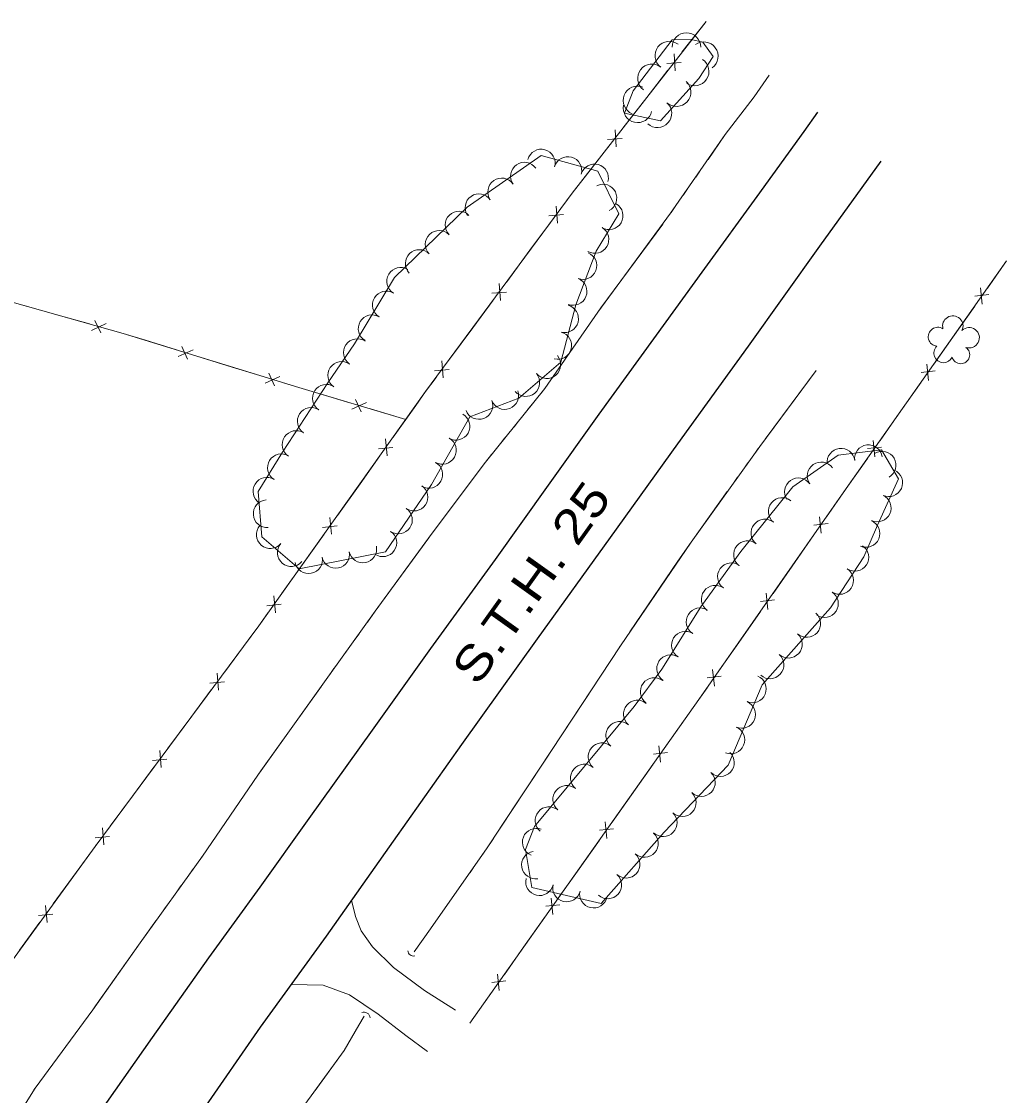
# Model space of a CAD drawing. Extents: x 296677 to 299172, y 46050 to 48373.
# Drawn here: x 298156.8 to 298443.9, y 47221.8 to 47534.8 of the extents above; entities that cross this region are included whole.
import ezdxf

# ---------------------------------------------------------------- set-up
doc = ezdxf.new("R2010")
doc.units = 0
doc.header["$LTSCALE"] = 2.4
doc.linetypes.add('LONG_DASHED', pattern=[7.5, 6, -1.5])
for name, color, linetype, lineweight in [('11', 7, 'Continuous', 25), ('15', 7, 'Continuous', 13), ('17', 7, 'LONG_DASHED', 13), ('18', 7, 'Continuous', 13), ('19', 7, 'Continuous', 13)]:
    doc.layers.add(name, color=color, linetype=linetype, lineweight=lineweight)

msp = doc.modelspace()

# ---------------------------------------------------------------- linework, layer by layer
at = {"layer": '11'}
for points in [[(298144.819, 47166.218), (298158.695, 47187.074), (298169.307, 47202.119), (298181.702, 47219.814), (298194.94, 47238.763), (298211.359, 47261.966), (298226.359, 47282.562), (298240.69, 47302.559), (298259.095, 47328.281), (298276.105, 47352.106), (298294.952, 47377.993), (298310.4, 47399.704), (298325.208, 47420.351), (298341.132, 47442.362), (298355.987, 47462.841), (298371.207, 47483.789), (298384.92, 47502.725), (298388.911, 47508.371)], [(298019.649, 46909.369), (298032.706, 46934.301), (298046.486, 46959.382), (298060.266, 46984.166), (298075.743, 47010.457), (298090.987, 47036.558), (298105.83, 47061.356), (298119.928, 47084.202), (298135.395, 47108.043), (298152.172, 47133.361), (298169.529, 47159.369), (298189.917, 47189.118), (298209.655, 47217.416), (298226.429, 47241.723), (298245.674, 47268.289), (298265.185, 47295.988), (298285.166, 47324.097), (298307.161, 47354.894), (298328.486, 47384.422), (298348.071, 47411.701), (298368.67, 47440.188), (298389.533, 47469.344), (298407.334, 47494.128)]]:
    msp.add_lwpolyline(points, dxfattribs=at)
at = {"layer": '15'}
for p, q in [((298349.315, 47525.805), (298356.323, 47534.793)), ((298347.34, 47520.423), (298347.069, 47525.379)), ((298344.873, 47522.563), (298349.122, 47522.82)), ((298339.077, 47512.673), (298345.241, 47520.579)), ((298332.07, 47503.685), (298339.077, 47512.673)), ((298330.094, 47498.304), (298329.823, 47503.26)), ((298327.628, 47500.444), (298331.876, 47500.701)), ((298321.832, 47490.554), (298327.995, 47498.459)), ((298313.073, 47476.071), (298312.674, 47481.018)), ((298310.552, 47478.146), (298314.792, 47478.513)), ((298305.015, 47468.108), (298310.971, 47476.171)), ((298298.243, 47458.941), (298305.015, 47468.108)), ((298443.923, 47465.07), (298438.334, 47457.126)), ((298293.887, 47455.585), (298298.127, 47455.952)), ((298296.408, 47453.51), (298296.009, 47458.457)), ((298436.295, 47457.177), (298436.793, 47452.393)), ((298288.35, 47445.548), (298294.306, 47453.611)), ((298438.784, 47455.223), (298434.685, 47454.772)), ((298157.149, 47452.124), (298167.494, 47449.212)), ((298167.494, 47449.212), (298176.593, 47446.651)), ((298434.639, 47451.875), (298428.284, 47442.843)), ((298177.206, 47444.764), (298181.436, 47446.768)), ((298178.195, 47447.68), (298179.934, 47444.063)), ((298281.579, 47436.38), (298288.35, 47445.548)), ((298192.907, 47441.887), (298201.94, 47439.103)), ((298203.566, 47440.092), (298205.216, 47436.433)), ((298428.284, 47442.843), (298422.695, 47434.899)), ((298202.506, 47437.201), (298206.784, 47439.1)), ((298207.912, 47437.263), (298218.183, 47434.097)), ((298218.183, 47434.097), (298227.216, 47431.313)), ((298279.744, 47430.949), (298279.344, 47435.897)), ((298420.657, 47434.95), (298421.154, 47430.166)), ((298227.782, 47429.411), (298232.06, 47431.311)), ((298228.842, 47432.302), (298230.492, 47428.644)), ((298277.222, 47433.025), (298281.463, 47433.392)), ((298423.145, 47432.996), (298419.046, 47432.546)), ((298419, 47429.648), (298412.646, 47420.616)), ((298243.477, 47426.368), (298252.538, 47423.678)), ((298254.154, 47424.684), (298255.842, 47421.043)), ((298253.124, 47421.782), (298257.382, 47423.726)), ((298258.529, 47421.9), (298268.832, 47418.842)), ((298265.137, 47413.658), (298271.753, 47422.939)), ((298412.646, 47420.616), (298407.056, 47412.673)), ((298263.395, 47408.196), (298262.911, 47413.136)), ((298405.018, 47412.723), (298405.515, 47407.94)), ((298260.839, 47410.228), (298265.072, 47410.668)), ((298407.506, 47410.769), (298403.407, 47410.319)), ((298255.473, 47400.099), (298261.291, 47408.262)), ((298248.857, 47390.818), (298255.473, 47400.099)), ((298397.008, 47398.389), (298391.442, 47390.428)), ((298247.115, 47385.357), (298246.631, 47390.297)), ((298389.404, 47390.473), (298389.915, 47385.691)), ((298244.559, 47387.389), (298248.792, 47387.828)), ((298391.898, 47388.527), (298387.8, 47388.064)), ((298239.193, 47377.259), (298245.011, 47385.422)), ((298387.763, 47385.166), (298381.435, 47376.115)), ((298232.577, 47367.978), (298239.193, 47377.259)), ((298381.435, 47376.115), (298375.87, 47368.155)), ((298373.831, 47368.2), (298374.343, 47363.418)), ((298228.278, 47364.549), (298232.512, 47364.988)), ((298230.834, 47362.517), (298230.351, 47367.457)), ((298376.326, 47366.253), (298372.228, 47365.79)), ((298372.191, 47362.893), (298365.863, 47353.842)), ((298216.04, 47345.326), (298222.831, 47354.479)), ((298365.863, 47353.842), (298360.298, 47345.882)), ((298358.259, 47345.926), (298358.771, 47341.144)), ((298214.193, 47339.899), (298213.804, 47344.847)), ((298360.753, 47343.98), (298356.655, 47343.517)), ((298206.118, 47331.954), (298212.091, 47340.004)), ((298211.676, 47341.979), (298215.917, 47342.338)), ((298199.327, 47322.801), (298206.118, 47331.954)), ((298350.258, 47331.592), (298344.646, 47323.664)), ((298197.48, 47317.374), (298197.091, 47322.322)), ((298345.091, 47321.759), (298340.99, 47321.32)), ((298342.608, 47323.72), (298343.092, 47318.935)), ((298194.963, 47319.455), (298199.204, 47319.813)), ((298340.937, 47318.423), (298334.556, 47309.409)), ((298189.405, 47309.429), (298195.378, 47317.479)), ((298182.614, 47300.276), (298189.405, 47309.429)), ((298334.556, 47309.409), (298328.944, 47301.481)), ((298180.767, 47294.849), (298180.378, 47299.798)), ((298329.389, 47299.577), (298325.289, 47299.138)), ((298326.906, 47301.538), (298327.39, 47296.753)), ((298178.25, 47296.93), (298182.491, 47297.288)), ((298325.235, 47296.241), (298318.854, 47287.227)), ((298166.037, 47277.651), (298172.754, 47286.859)), ((298318.854, 47287.227), (298313.243, 47279.299)), ((298164.235, 47272.209), (298163.806, 47277.154)), ((298313.687, 47277.395), (298309.587, 47276.956)), ((298311.204, 47279.355), (298311.688, 47274.57)), ((298161.702, 47274.269), (298165.94, 47274.662)), ((298309.533, 47274.058), (298303.153, 47265.044)), ((298156.226, 47264.198), (298162.133, 47272.297)), ((298303.153, 47265.044), (298297.541, 47257.117)), ((298297.986, 47255.212), (298293.885, 47254.773)), ((298295.503, 47257.173), (298295.987, 47252.388)), ((298293.831, 47251.876), (298287.451, 47242.862))]:
    msp.add_line(p, q, dxfattribs=at)
for points in [[(297934.044, 46907.735), (297975.364, 46985.334), (298019.861, 47066.957), (298074.609, 47150.346), (298125.783, 47222.46), (298178.264, 47294.414), (298225.978, 47358.72), (298274.598, 47426.93), (298317.324, 47484.772), (298356.323, 47534.793)], [(298042.529, 47491.507), (298087.491, 47471.635), (298107.15, 47466.195), (298186.423, 47443.885), (298237.649, 47428.098), (298268.832, 47418.842)], [(298314.908, 47481.501), (298317.324, 47484.772), (298321.832, 47490.554)], [(298443.923, 47465.07), (298397.2, 47398.664), (298354.246, 47337.226), (298287.451, 47242.862)], [(298182.608, 47444.959), (298186.423, 47443.885), (298192.907, 47441.887)], [(298271.753, 47422.939), (298274.598, 47426.93), (298277.642, 47431.05)], [(298233.187, 47429.473), (298237.649, 47428.098), (298243.477, 47426.368)], [(298403.362, 47407.421), (298397.2, 47398.664), (298397.008, 47398.389)], [(298222.831, 47354.479), (298225.978, 47358.72), (298228.731, 47362.582)], [(298356.619, 47340.619), (298354.246, 47337.226), (298350.258, 47331.592)], [(298172.754, 47286.859), (298178.264, 47294.414), (298178.665, 47294.955)]]:
    msp.add_lwpolyline(points, dxfattribs=at)
for centre, radius, start, end in [((298270.984, 47264.039), 1.572, 180.22374, 286.46331), ((298256.634, 47244.296), 1.819, 5.64214, 111.88171)]:
    msp.add_arc(centre, radius, start, end, dxfattribs=at)
at = {"layer": '17'}
for points in [[(298283.319, 47246.66), (298274.283, 47252.382), (298265.205, 47259.152), (298259.09, 47265.157), (298255.821, 47269.848), (298254.131, 47273.971), (298253.027, 47278.728)], [(298235.42, 47254.134), (298244.685, 47253.981), (298252.402, 47251.192), (298260.795, 47245.485), (298268.79, 47239.359), (298275.107, 47234.605)]]:
    msp.add_lwpolyline(points, dxfattribs=at)
at = {"layer": '18'}
for points in [[(298346.425, 47529.485), (298335.078, 47514.566), (298332.53, 47508.085), (298343.077, 47505.811), (298354.279, 47518.184), (298358.455, 47524.555), (298355.404, 47528.747), (298351.967, 47529.499)], [(298232.859, 47409.299), (298225.764, 47397.796), (298226.806, 47384.622), (298237.752, 47375.251), (298262.88, 47380.238), (298276.283, 47399.897), (298287.443, 47419.61), (298301.761, 47425.066), (298314.031, 47435.526), (298318.335, 47452.24), (298324.353, 47467.824), (298330.887, 47478.756), (298324.777, 47491.144), (298308.319, 47495.727), (298286.724, 47480.724), (298265.481, 47460.176), (298253.906, 47440.873), (298246.078, 47429.524)], [(298306.352, 47300.17), (298303.713, 47293.475), (298305.546, 47282.478), (298325.747, 47277.826), (298344.148, 47298.588), (298362.769, 47318.135), (298372.656, 47341.527), (298392.568, 47363.94), (298402.348, 47378.82), (298406.272, 47388.011), (298412.428, 47401.483), (298407.47, 47409.997), (298394.823, 47408.393), (298381.673, 47399.225), (298366.446, 47380.37), (298354.834, 47364.244), (298343.448, 47346.079), (298335.358, 47335.144)]]:
    msp.add_lwpolyline(points, close=True, dxfattribs=at)
for centre, radius, start, end in [((298350.599, 47527.313), 4.17, 0.1524, 180.13708), ((298345.638, 47524.845), 4.17, 52.75199, 232.73667), ((298355.668, 47524.675), 4.17, 306.05535, 126.04003), ((298340.59, 47518.207), 4.17, 52.75199, 232.73667), ((298353.011, 47520.23), 4.17, 236.76402, 56.7487), ((298336.339, 47511.809), 4.17, 68.54543, 248.53011), ((298347.746, 47514.22), 4.17, 227.85128, 47.83596), ((298336.391, 47509.485), 4.17, 167.84058, 347.82526), ((298342.149, 47508.038), 4.17, 227.85128, 47.83596), ((298308.307, 47493.54), 4.031, 344.44693, 164.43161), ((298303.375, 47489.723), 4.031, 34.79708, 214.78176), ((298316.072, 47491.378), 4.031, 344.44693, 164.43161), ((298323.838, 47489.216), 4.031, 344.44693, 164.43161), ((298296.755, 47485.124), 4.031, 34.79708, 214.78176), ((298326.279, 47483.329), 4.031, 296.26106, 116.24574), ((298290.135, 47480.525), 4.031, 34.79708, 214.78176), ((298328.091, 47478.189), 4.031, 239.14112, 59.1258), ((298284.329, 47475.472), 4.031, 44.0549, 224.03958), ((298323.955, 47471.27), 4.031, 239.14112, 59.1258), ((298278.535, 47469.868), 4.031, 44.0549, 224.03958), ((298272.741, 47464.263), 4.031, 44.0549, 224.03958), ((298320.473, 47463.634), 4.031, 248.89283, 68.87751), ((298267.29, 47459.09), 4.031, 59.05875, 239.04343), ((298317.569, 47456.114), 4.031, 248.89283, 68.87751), ((298263.145, 47452.177), 4.031, 59.05875, 239.04343), ((298258.999, 47445.264), 4.031, 59.05875, 239.04343), ((298315.114, 47448.193), 4.031, 255.56723, 75.55191), ((298428.267, 47446.035), 2.974, 334.0166, 195.25048), ((298313.104, 47440.386), 4.031, 255.56723, 75.55191), ((298423.885, 47442.924), 2.777, 56.98749, 264.76048), ((298433.034, 47442.636), 2.975, 251.66742, 134.64069), ((298254.691, 47438.296), 4.031, 55.4116, 235.39628), ((298425.553, 47438.145), 2.783, 133.66451, 334.67555), ((298430.574, 47437.691), 2.611, 196.37265, 54.30526), ((298309.934, 47434.806), 4.031, 220.45478, 40.43946), ((298250.114, 47431.66), 4.031, 55.4116, 235.39628), ((298303.8, 47429.576), 4.031, 220.45478, 40.43946), ((298245.65, 47425.013), 4.031, 56.83915, 236.82383), ((298290.129, 47422.891), 4.031, 200.86744, 20.85212), ((298297.661, 47425.761), 4.031, 200.86744, 20.85212), ((298241.24, 47418.265), 4.031, 56.83915, 236.82383), ((298283.448, 47416.836), 4.031, 240.49242, 60.4771), ((298236.83, 47411.518), 4.031, 56.83915, 236.82383), ((298279.477, 47409.821), 4.031, 240.49242, 60.4771), ((298232.539, 47404.761), 4.031, 58.34156, 238.32624), ((298395.668, 47406.372), 4.035, 7.23581, 187.22049), ((298403.673, 47407.387), 4.035, 7.23581, 187.22049), ((298407.645, 47405.501), 4.035, 300.2214, 120.20608), ((298275.506, 47402.806), 4.031, 240.49242, 60.4771), ((298389.891, 47402.38), 4.035, 34.89134, 214.87602), ((298409.597, 47400.369), 4.035, 245.44974, 65.43442), ((298228.307, 47397.9), 4.031, 58.34156, 238.32624), ((298271.209, 47396.201), 4.031, 235.7225, 55.70718), ((298383.272, 47397.766), 4.035, 34.89134, 214.87602), ((298378.547, 47391.992), 4.035, 51.08387, 231.06854), ((298406.244, 47393.031), 4.035, 245.44974, 65.43442), ((298228.39, 47391.346), 4.031, 94.53007, 274.51474), ((298266.669, 47389.54), 4.031, 235.7225, 55.70718), ((298373.477, 47385.715), 4.035, 51.08387, 231.06854), ((298229.305, 47385.26), 4.031, 139.44044, 319.42512), ((298402.95, 47385.608), 4.035, 246.88812, 66.87279), ((298262.128, 47382.88), 4.031, 235.7225, 55.70718), ((298368.408, 47379.438), 4.035, 51.08387, 231.06854), ((298235.428, 47380.018), 4.031, 139.44044, 319.42512), ((298256.289, 47381.081), 4.031, 191.23294, 11.21762), ((298399.71, 47378.651), 4.035, 236.69242, 56.6771), ((298240.475, 47377.942), 4.031, 191.23294, 11.21762), ((298248.382, 47379.512), 4.031, 191.23294, 11.21762), ((298363.741, 47373), 4.035, 54.25078, 234.23546), ((298395.278, 47371.909), 4.035, 236.69242, 56.6771), ((298359.026, 47366.452), 4.035, 54.25078, 234.23546), ((298390.847, 47365.166), 4.035, 236.69242, 56.6771), ((298354.591, 47359.88), 4.035, 57.92777, 237.91245), ((298385.683, 47359.37), 4.035, 228.38936, 48.37404), ((298350.306, 47353.044), 4.035, 57.92777, 237.91245), ((298380.324, 47353.338), 4.035, 228.38936, 48.37404), ((298346.021, 47346.207), 4.035, 57.92777, 237.91245), ((298374.965, 47347.306), 4.035, 228.38936, 48.37404), ((298341.224, 47339.522), 4.035, 53.51265, 233.49733), ((298369.849, 47340.309), 4.035, 247.09554, 67.08022), ((298336.307, 47332.98), 4.035, 50.33674, 230.32142), ((298366.707, 47332.877), 4.035, 247.09554, 67.08022), ((298331.156, 47326.769), 4.035, 50.33674, 230.32142), ((298363.566, 47325.445), 4.035, 247.09554, 67.08022), ((298326.005, 47320.559), 4.035, 50.33674, 230.32142), ((298360.533, 47318.85), 4.035, 226.39745, 46.38213), ((298320.854, 47314.348), 4.035, 50.33674, 230.32142), ((298354.968, 47313.008), 4.035, 226.39745, 46.38213), ((298315.703, 47308.137), 4.035, 50.33674, 230.32142), ((298349.403, 47307.165), 4.035, 226.39745, 46.38213), ((298310.553, 47301.927), 4.035, 50.33674, 230.32142), ((298343.837, 47301.323), 4.035, 226.39745, 46.38213), ((298306.837, 47295.642), 4.035, 68.49456, 248.47923), ((298338.387, 47295.272), 4.035, 228.45765, 48.44232), ((298306.603, 47288.982), 4.035, 99.47083, 279.45551), ((298333.036, 47289.234), 4.035, 228.45765, 48.44232), ((298307.8, 47284.126), 4.035, 167.03936, 347.02403), ((298327.684, 47283.195), 4.035, 228.45765, 48.44232), ((298315.663, 47282.315), 4.035, 167.03936, 347.02403), ((298323.526, 47280.505), 4.035, 167.03936, 347.02403)]:
    msp.add_arc(centre, radius, start, end, dxfattribs=at)
at = {"layer": '19'}
for p, q in [((298353.336, 47489.46), (298354.53, 47491.179)), ((298349.755, 47484.301), (298350.949, 47486.02)), ((298346.174, 47479.142), (298347.368, 47480.861)), ((298325.664, 47451.349), (298343.694, 47475.769)), ((298373.592, 47413.112), (298388.409, 47433.121)), ((298304.295, 47421.612), (298305.609, 47423.242)), ((298300.355, 47416.721), (298301.668, 47418.351)), ((298296.415, 47411.831), (298297.728, 47413.461)), ((298370.554, 47408.953), (298371.557, 47410.347)), ((298367.546, 47404.77), (298368.549, 47406.165)), ((298364.539, 47400.588), (298365.541, 47401.982)), ((298334.141, 47356.895), (298348.143, 47377.484)), ((298253.979, 47354.7), (298255.202, 47356.398)), ((298250.309, 47349.605), (298251.533, 47351.303)), ((298328.413, 47348.332), (298329.358, 47349.766)), ((298246.64, 47344.51), (298247.863, 47346.208)), ((298325.578, 47344.03), (298326.523, 47345.464)), ((298226.576, 47316.397), (298244.207, 47341.102)), ((298296.258, 47299.601), (298309.985, 47320.374)), ((298293.418, 47295.304), (298294.365, 47296.736)), ((298290.493, 47291.064), (298291.48, 47292.469)), ((298205.719, 47286.286), (298206.94, 47287.986)), ((298287.531, 47286.848), (298288.519, 47288.253)), ((298202.055, 47281.185), (298203.276, 47282.886)), ((298198.392, 47276.084), (298199.613, 47277.785))]:
    msp.add_line(p, q, dxfattribs=at)
for points in [[(298147.625, 47203.168), (298160.73, 47224.002), (298177.602, 47246.84), (298191.385, 47266.329), (298209.526, 47291.587), (298225.683, 47315.146), (298246.578, 47344.424), (298259.93, 47362.962), (298276.211, 47385.269), (298291.999, 47406.35), (298309.331, 47427.862), (298324.753, 47450.116), (298346.019, 47478.918), (298361.946, 47501.864), (298370.33, 47512.82), (298374.73, 47519.182)], [(298356.917, 47494.618), (298361.946, 47501.864), (298370.33, 47512.82), (298374.73, 47519.182)], [(298308.236, 47426.502), (298309.331, 47427.862), (298324.753, 47450.116), (298325.664, 47451.349)], [(298271.269, 47263.68), (298276.007, 47270.442), (298292.575, 47294.028), (298311.323, 47322.399), (298331.403, 47352.869), (298351.962, 47383.101), (298371.982, 47410.938), (298388.409, 47433.121)], [(298275.524, 47384.327), (298276.211, 47385.269), (298291.999, 47406.35), (298293.788, 47408.57)], [(298348.143, 47377.484), (298351.962, 47383.101), (298362.534, 47397.8)], [(298257.649, 47359.795), (298259.93, 47362.962), (298275.524, 47384.327)], [(298331.248, 47352.633), (298331.403, 47352.869), (298332.21, 47354.055)], [(298309.985, 47320.374), (298311.323, 47322.399), (298323.688, 47341.163)], [(298209.382, 47291.387), (298209.526, 47291.587), (298225.683, 47315.146), (298226.576, 47316.397)], [(298271.269, 47263.68), (298276.007, 47270.442), (298285.557, 47284.038)], [(298178.379, 47247.939), (298191.385, 47266.329), (298195.949, 47272.684)], [(298160.405, 47223.486), (298160.73, 47224.002), (298177.602, 47246.84), (298178.379, 47247.939)], [(298107.322, 47001.324), (298117.849, 47020.236), (298131.431, 47045.573), (298141.828, 47062.14), (298151.503, 47080.373), (298158.084, 47094.754), (298166.888, 47109.501), (298181.763, 47130.176), (298193.198, 47148.329), (298207.14, 47170.844), (298218.166, 47189.253), (298229.804, 47206.087), (298241.266, 47221.699), (298250.81, 47234.929), (298255.094, 47242.343), (298256.656, 47244.904)], [(298242.4, 47223.271), (298250.81, 47234.929), (298255.094, 47242.343), (298256.656, 47244.904)]]:
    msp.add_lwpolyline(points, dxfattribs=at)

# ---------------------------------------------------------------- texts
at = {"layer": '11', "width": 1.2}
msp.add_text('S.T.H. 25', height=10, rotation=54.466, dxfattribs=at).set_placement((298289.732, 47340.814))

doc.saveas('drawing.dxf')
